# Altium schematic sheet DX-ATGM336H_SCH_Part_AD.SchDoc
size A4; SheetNumber: 1; SheetTotal: 1
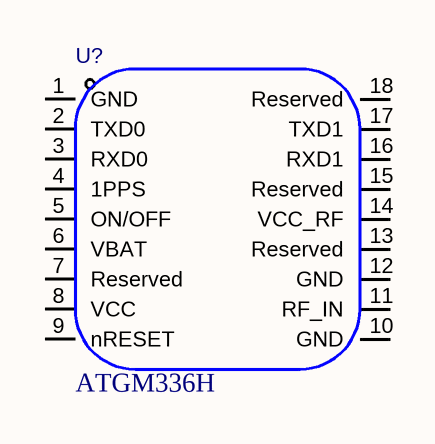
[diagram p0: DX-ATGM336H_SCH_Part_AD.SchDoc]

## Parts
U?  ATGM336H

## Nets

Not connected (* = marked no-connect by the designer): U? 1(GND) 2(TXD0) 3(RXD0) 4(1PPS) 5(ON/OFF) 6(VBAT) 7(Reserved) 8(VCC) 9(nRESET) 10(GND) 11(RF_IN) 12(GND) 13(Reserved) 14(VCC_RF) 15(Reserved) 16(RXD1) 17(TXD1) 18(Reserved)

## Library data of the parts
U? = ATGM336H: Symbol: ATGM336H-6N-22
